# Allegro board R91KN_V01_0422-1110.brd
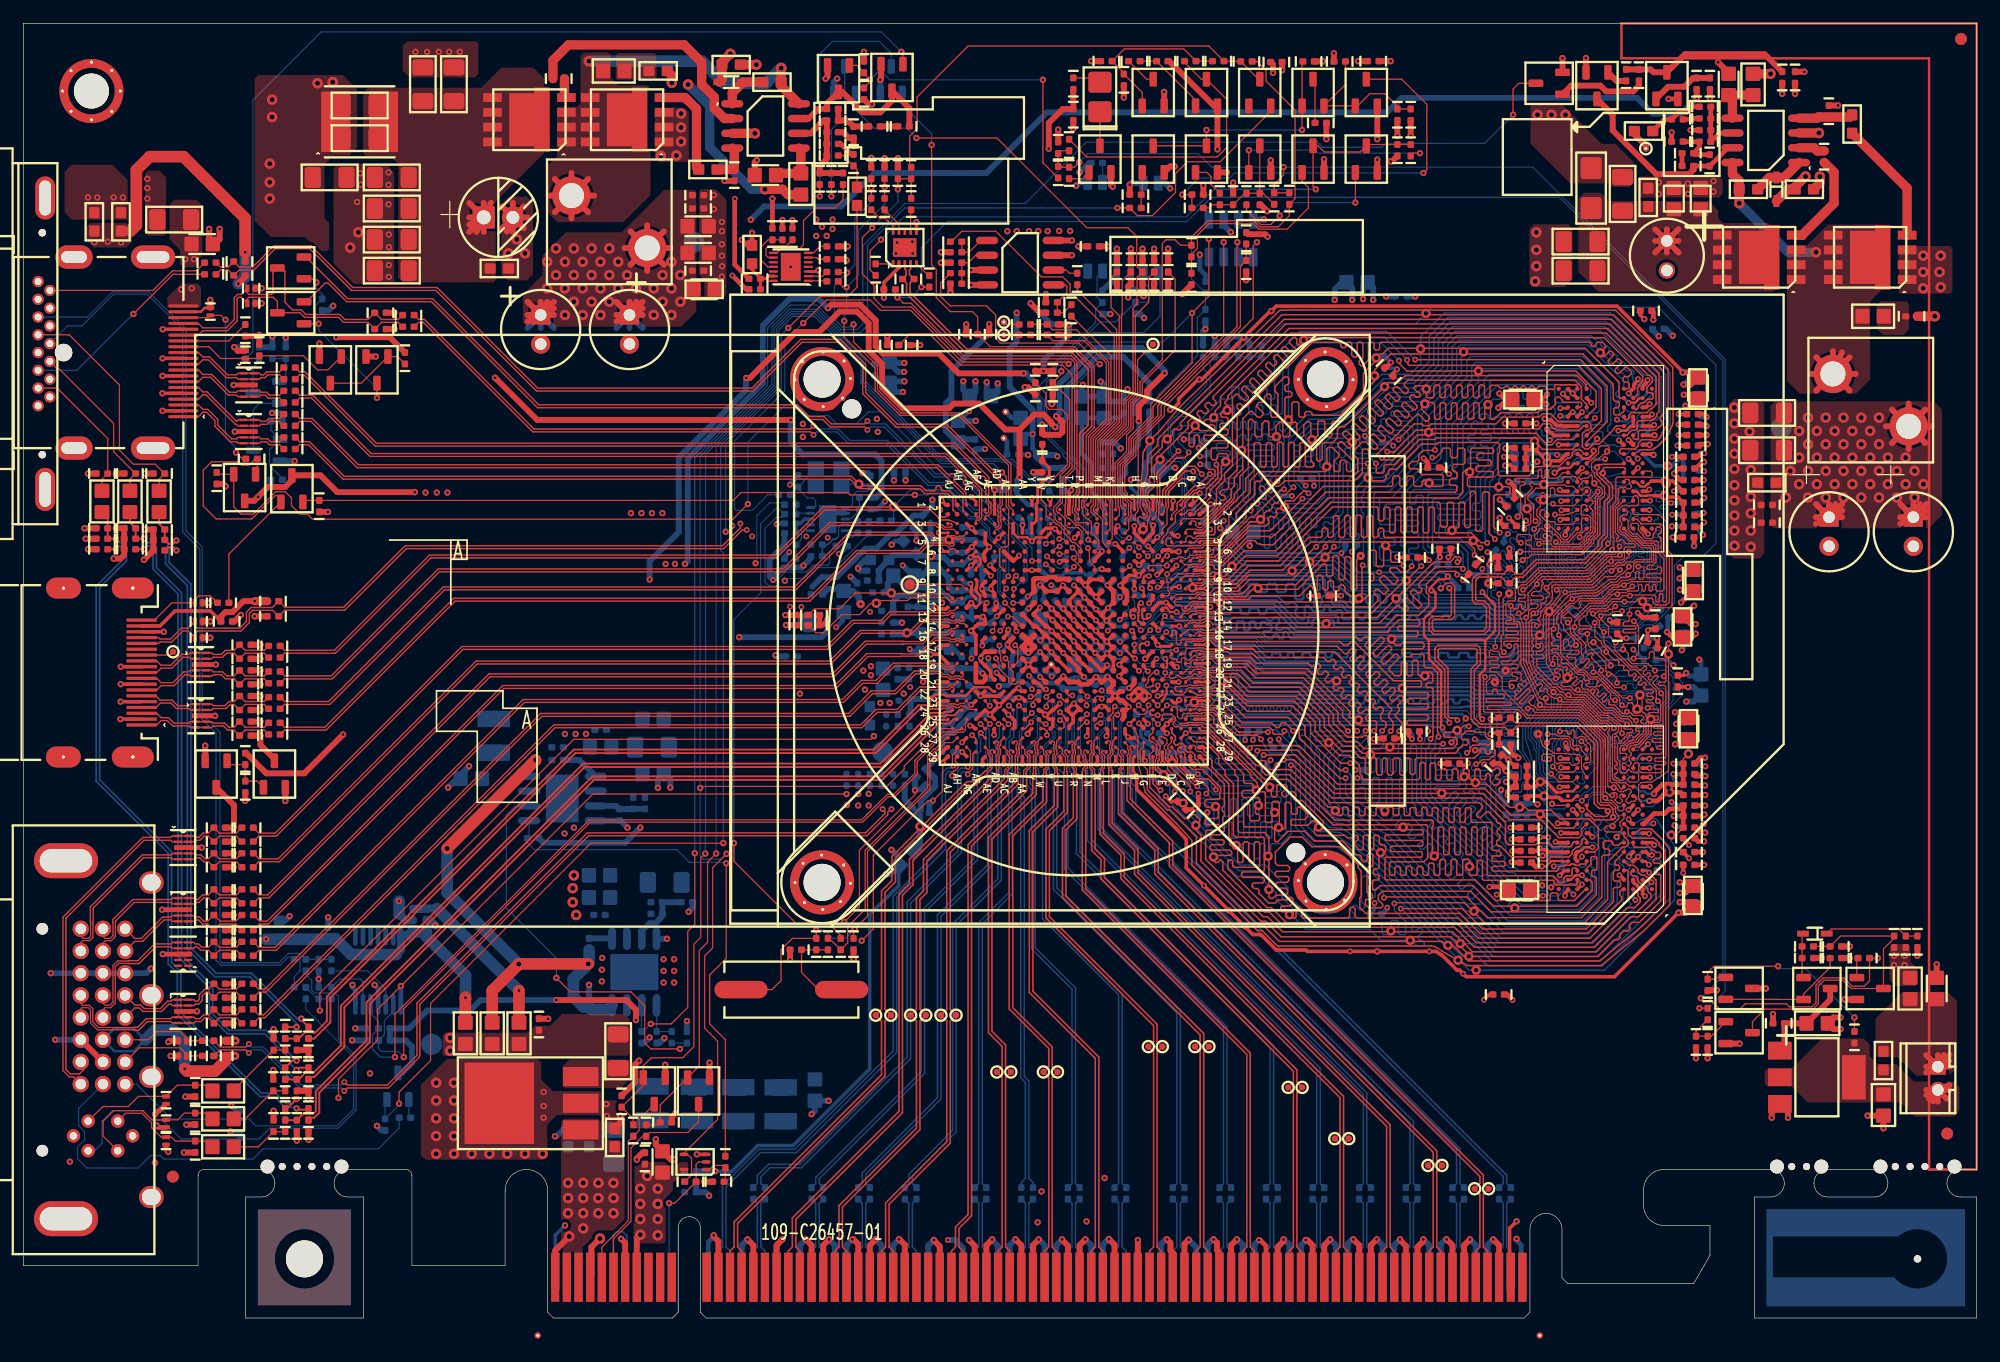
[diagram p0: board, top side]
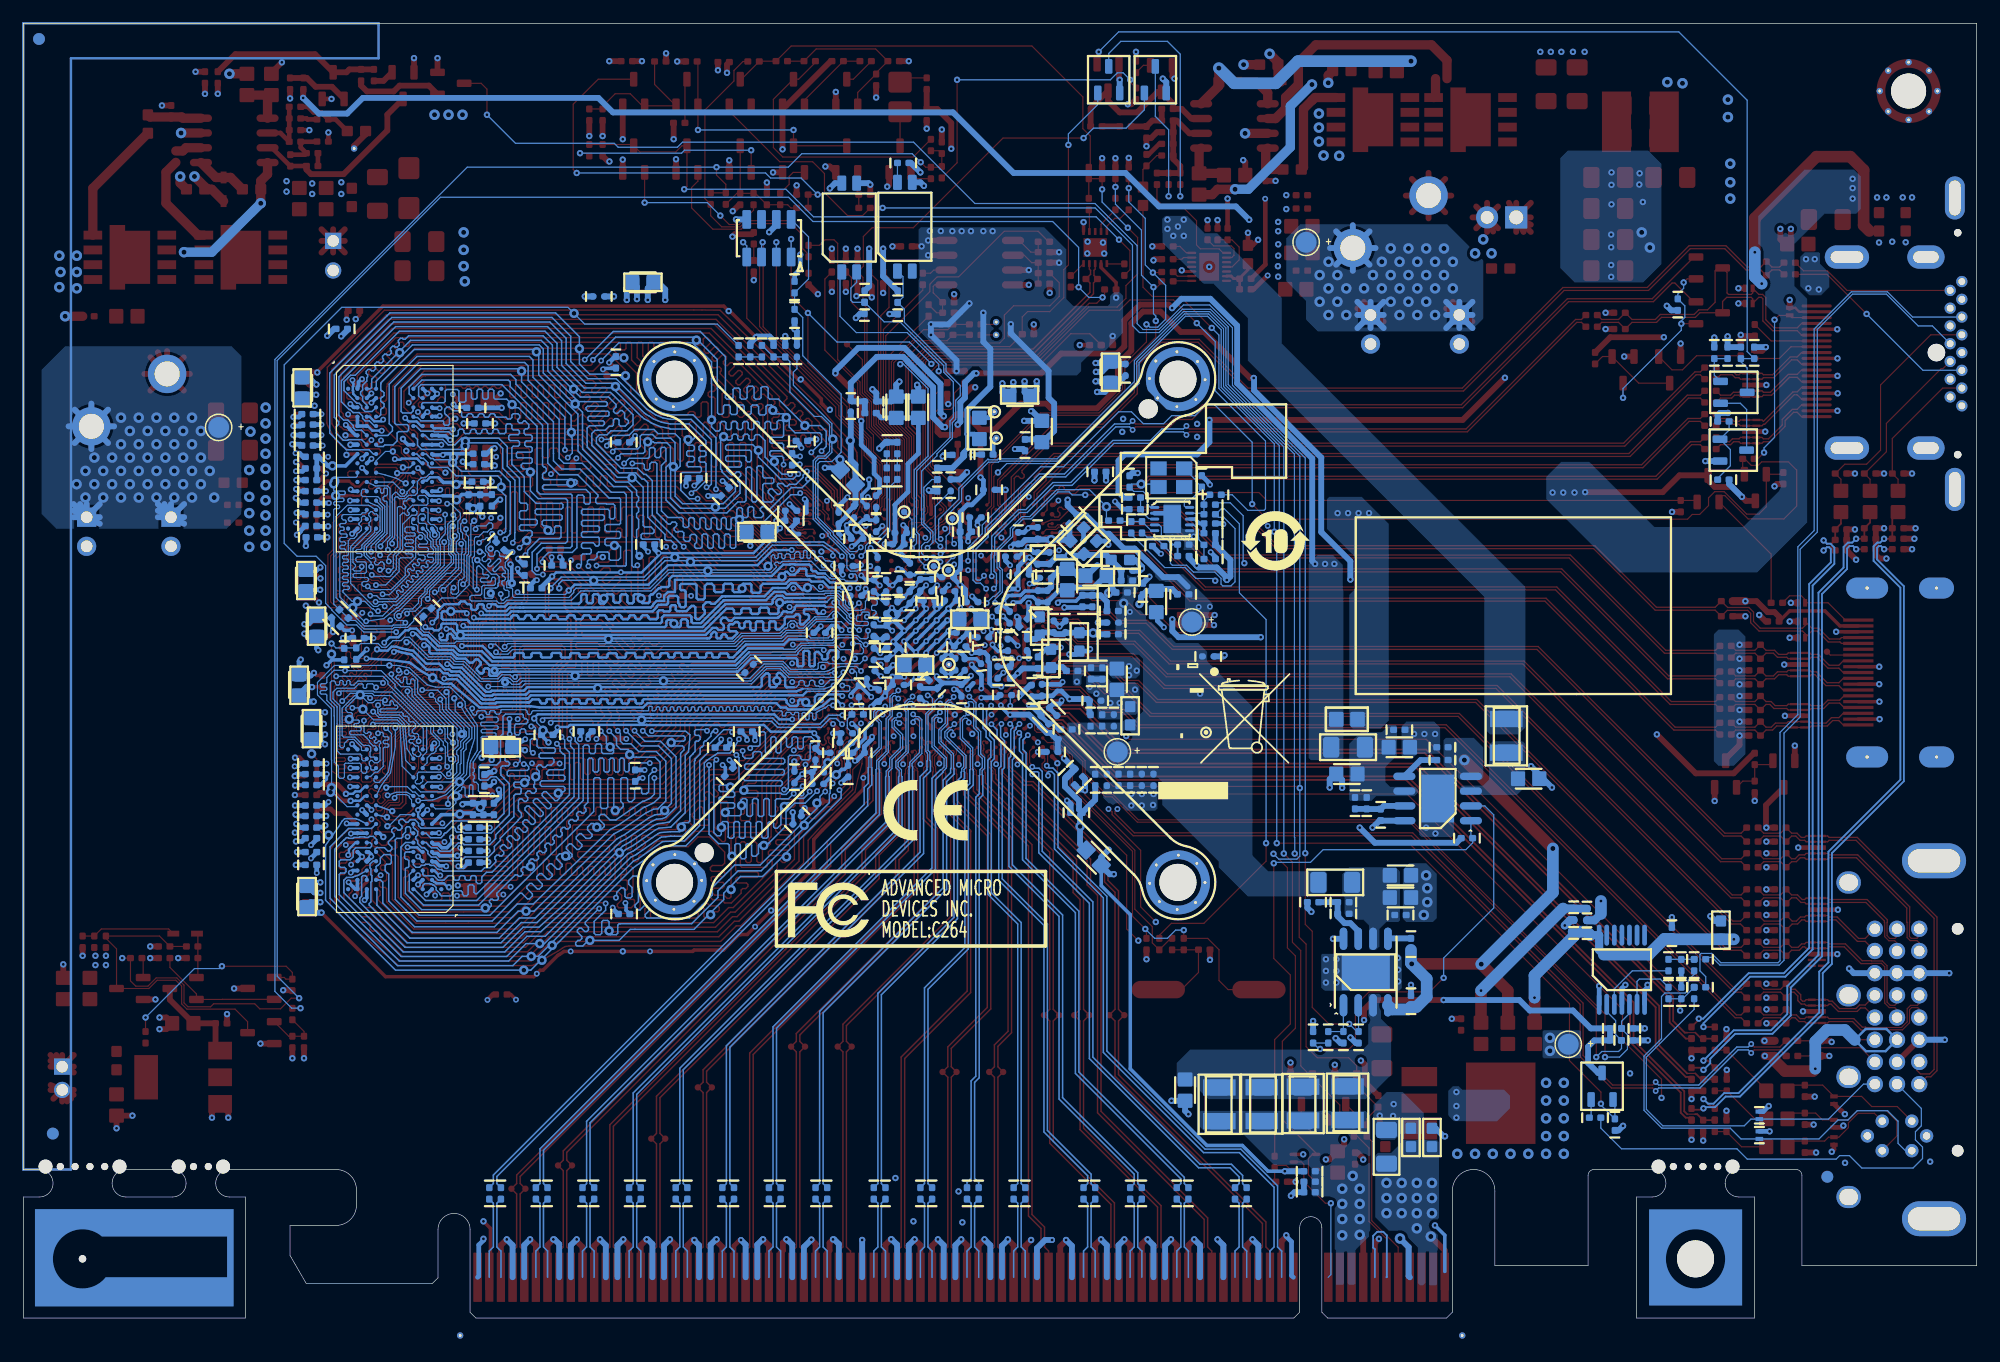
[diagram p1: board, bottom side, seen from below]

Outline 167.64 x 111.15 mm; copper layers: TOP, L2_INNER, L3_INNER, BOTTOM. Coordinates in mm from the lower left corner of the outline.
Outline path: 0,111.15 167.64,111.15 167.64,12.75 166.3,12.75 arc(165.09,11.58) 166.28,10.39 167.64,10.39 167.64,0 148.59,0 148.59,10.39 149.95,10.39 arc(150.78,10.74) 151.13,11.57 arc(150.78,12.4) 149.95,12.75 140.8,12.75 arc(139.56,12.24) 139.05,11 139.05,9.7 arc(139.56,8.46) 140.8,7.95 144.75,7.95 144.75,5.37 143.35,2.95 132.55,2.95 132.05,3.45 132.05,7.61 arc(131.65,8.58) 130.68,8.98 arc(129.7,8.58) 129.3,7.61 129.3,0.5 128.8,0 58.6,0 58.1,0.5 58.1,7.8 arc(57.15,8.7) 56.2,7.8 56.2,0.5 55.7,0 45.5,0 45,0.5 45,10.9 arc(43.17,12.75) 41.35,10.9 41.35,4.5 33.35,4.5 33.35,12.24 arc(33.2,12.6) 32.84,12.75 27.85,12.75 arc(26.67,11.57) 27.85,10.39 29.21,10.39 29.21,0 19.05,0 19.05,10.39 20.41,10.39 arc(21.24,10.74) 21.59,11.57 arc(21.24,12.4) 20.41,12.75 15.51,12.75 arc(15.15,12.6) 15,12.24 15,4.5 0,4.5 0,111.15 ; 153.67,11.57 arc(154.02,12.4) 154.85,12.75 158.84,12.75 arc(160.02,11.57) 158.84,10.39 154.85,10.39 arc(154.02,10.74) 153.67,11.57

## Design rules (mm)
net group A_VSYNC_DAC2: nets A_HSYNC_DAC2 A_VSYNC_DAC2
net group AUX2: nets AUX2N AUX2P
net group DDC1CLK: nets DDC1CLK DDC1DATA
net group DDC2CLK: nets DDC2CLK DDC2DATA
net group DDC3CLK: nets DDC3CLK DDC3DATA
net group DDC5CLK_AUX5P: nets DDC5CLK_AUX5P DDC5DATA_AUX5N
net group DPA_0: nets DPA_0N DPA_0P
net group DPA_1: nets DPA_1N DPA_1P
net group DPA_2P: nets DPA_2N DPA_2P
net group DPA_3P: nets DPA_3N DPA_3P
net group DPA_A0: nets DPA_A0N DPA_A0P
net group DPA_A1: nets DPA_A1N DPA_A1P
net group DPA_A2: nets DPA_A2N DPA_A2P
net group DPA_A3: nets DPA_A3N DPA_A3P
net group DPB_0: nets DPB_0N DPB_0P
net group DPB_1: nets DPB_1N DPB_1P
net group DPB_2: nets DPB_2N DPB_2P
net group DPB_3: nets DPB_3N DPB_3P
net group EFTX0M: nets EFTX0M EFTX0P
net group EFTX1M: nets EFTX1M EFTX1P
net group EFTX2M: nets EFTX2M EFTX2P
net group EFTX3M: nets EFTX3M EFTX3P
net group EFTX4M: nets EFTX4M EFTX4P
net group EFTX5M: nets EFTX5M EFTX5P
net group FB: nets NFB PFB
net group MEM_CALR0: nets MEM_CALRN0 MEM_CALRP0
net group PCIE_CALR: nets PCIE_CALRN PCIE_CALRP
net group PCIE_PH: nets GPU_DMINUS GPU_DPLUS
net group PER0: nets PERN0 PERP0
net group PER1: nets PERN1 PERP1
net group PER2: nets PERN2 PERP2
net group PER3: nets PERN3 PERP3
net group PER4: nets PERN4 PERP4
net group PER5: nets PERN5 PERP5
net group PER6: nets PERN6 PERP6
net group PER7: nets PERN7 PERP7
net group PER8: nets PERN8 PERP8
net group PER9: nets PERN9 PERP9
net group PER10: nets PERN10 PERP10
net group PER11: nets PERN11 PERP11
net group PER12: nets PERN12 PERP12
net group PER13: nets PERN13 PERP13
net group PER14: nets PERN14 PERP14
net group PER15: nets PERN15 PERP15
net group DVP_R: nets GENERICC GENERICD GPIO_1 GPIO_2 GPIO_3_SMBDATA GPIO_4_SMBCLK GPIO_5 GPIO_8_SO
net group M_DQMA#: nets M_DQMA#0 M_DQMA#1 M_DQMA#2 M_DQMA#3 M_DQMA#4 M_DQMA#5 M_DQMA#6 M_DQMA#7
net group M_MAA: nets M_MAA0 M_MAA1 M_MAA2 M_MAA3 M_MAA4 M_MAA5 M_MAA6 M_MAA7 M_MAA8 M_MAA9 M_MAA10 M_MAA11 M_MAA12 M_MAA13 M_MAA14
net group M_MDA: nets M_MDA0 M_MDA1 M_MDA2 M_MDA3 M_MDA4 M_MDA5 M_MDA6 M_MDA7 M_MDA8 M_MDA9 M_MDA10 M_MDA11 M_MDA12 M_MDA13 M_MDA14 M_MDA15 M_MDA16 M_MDA17 M_MDA18 M_MDA19 M_MDA20 M_MDA21 M_MDA22 M_MDA23 M_MDA24 M_MDA25 M_MDA26 M_MDA27 M_MDA28 M_MDA29 M_MDA30 M_MDA31 M_MDA32 M_MDA33 M_MDA34 M_MDA35 M_MDA36 M_MDA37 M_MDA38 M_MDA39 M_MDA40 M_MDA41 M_MDA42 M_MDA43 M_MDA44 M_MDA45 M_MDA46 M_MDA47 M_MDA48 M_MDA49 M_MDA50 M_MDA51 M_MDA52 M_MDA53 M_MDA54 M_MDA55 M_MDA56 M_MDA57 M_MDA58 M_MDA59 M_MDA60 M_MDA61 M_MDA62 M_MDA63
net group M_QSA: nets M_QSA0 M_QSA1 M_QSA2 M_QSA3 M_QSA4 M_QSA5 M_QSA6 M_QSA7
net group M_QSA#: nets M_QSA#0 M_QSA#1 M_QSA#2 M_QSA#3 M_QSA#4 M_QSA#5 M_QSA#6 M_QSA#7
net group MEM_ADD: nets BA0 BA1 BA2 CASA#0 CASA#1 CKEA0 CKEA1 CSA#0_0 CSA#1_0 ODTA0 RASA#0 RASA#1 WEA#0 WEA#1
net group MEM_CLK: nets CLKA0 CLKA1 CLKA#0 CLKA#1
net group NET_PERST#: nets PERST#
net group NET_PRESENCE: nets PRESENCE
net group PCIE_SP: nets PCIE_REFCLKN PCIE_REFCLKP PCIE_TX0N PCIE_TX0P PCIE_TX1N PCIE_TX1P PCIE_TX2N PCIE_TX2P PCIE_TX3N PCIE_TX3P PCIE_TX4N PCIE_TX4P PCIE_TX5N PCIE_TX5P PCIE_TX6N PCIE_TX6P PCIE_TX7N PCIE_TX7P PCIE_TX8N PCIE_TX8P PCIE_TX9N PCIE_TX9P PCIE_TX10N PCIE_TX10P PCIE_TX11N PCIE_TX11P PCIE_TX12N PCIE_TX12P PCIE_TX13N PCIE_TX13P PCIE_TX14N PCIE_TX14P PCIE_TX15N PCIE_TX15P PETN0_GFXRN0 PETN1_GFXRN1 PETN2_GFXRN2 PETN3_GFXRN3 PETN4_GFXRN4 PETN5_GFXRN5 PETN6_GFXRN6 PETN7_GFXRN7 PETN8_GFXRN8 PETN9_GFXRN9 PETN10_GFXRN10 PETN11_GFXRN11 PETN12_GFXRN12 PETN13_GFXRN13 PETN14_GFXRN14 PETN15_GFXRN15 PETP0_GFXRP0 PETP1_GFXRP1 PETP2_GFXRP2 PETP3_GFXRP3 PETP4_GFXRP4 PETP5_GFXRP5 PETP6_GFXRP6 PETP7_GFXRP7 PETP8_GFXRP8 PETP9_GFXRP9 PETP10_GFXRP10 PETP11_GFXRP11 PETP12_GFXRP12 PETP13_GFXRP13 PETP14_GFXRP14 PETP15_GFXRP15
net group RGB: nets A_B_DAC1 A_BB_DAC1 A_G_DAC1 A_GB_DAC1 A_R_DAC1 A_RB_DAC1 B_DAC2 BB_DAC2 G_DAC2 GB_DAC2 R_DAC2 RB_DAC2
net group TMDS: nets DPB_AUXN DPB_AUXP DPB_C0N DPB_C0P DPB_C1N DPB_C1P DPB_C2N DPB_C2P DPB_C3N DPB_C3P DPE_TX0N DPE_TX0P DPE_TX1N DPE_TX1P DPE_TX2N DPE_TX2P DPE_TXCAN DPE_TXCAP DPF_TX3N DPF_TX3P DPF_TX4N DPF_TX4P DPF_TX5N DPF_TX5P EFTXCM EFTXCP
nets with their own width: min track width 0.3; nets +MVDD

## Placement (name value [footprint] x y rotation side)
B2  BLM15BD121SN1  [SMIND1005_0_5H]  78.11 50.53 270 bottom
B5  BLM15BD121SN1  [SMIND1005_0_5H]  96.63 78.29 180 bottom
B6  BLM15BD121SN1  [SMIND1005_0_5H]  76.05 51.3 0 bottom
B7  BLM15BD121SN1  [SMIND1005_0_5H]  73.38 62.28 270 bottom
B8  BLM15BD121SN1  [SMIND1005_0_5H]  68.1 62.12 270 bottom
B9  BLM15BD121SN1  [SMIND1005_0_5H]  94.45 70.1 179.8 bottom
B11  BLM15BD121SN1  [SMIND1005_0_5H]  75.65 46.2 180 bottom
B12  BLM15BD121SN1  [SMIND1005_0_5H]  94.93 77.69 90 bottom
B71  BLM15BD121SN1  [SMIND1005_0_5H]  68.08 65.42 270 bottom
B72  BLM15BD121SN1  [SMIND1005_0_5H]  65.83 67.38 270 bottom
B702  60R  [IND_3216_4515]  134.55 97 180 top
B800  BLM15AG121SN1D  [SMIND1005_0_5H]  86.75 67.5 90 bottom
B801  BLM15AG121SN1D  [SMIND1005_0_5H]  87.45 75.5 0 top
B850  220R_2A  [RES1608_2012_1_1H]  54.05 51.4 90 bottom
B1500  BLM15AG121SN1D  [SMIND1005_0_5H]  74.15 58.7 270 bottom
B1502  BLM15BD121SN1  [SMIND1005_0_5H]  77.63 55.55 270 bottom
B2503  BLM15AG121SN1D  [SMIND1005_0_5H]  72.93 63.31 270 bottom
B2505  BLM15BD121SN1  [SMIND1005_0_5H]  77.52 68.55 225 bottom
B4001  26R_600mA  [RES1608_2012_1_1H]  161.93 28.29 0 top
C3  0.1uF  [CAP1005_0_55H]  62.65 10.7 180 bottom
C4  0.1uF  [CAP1005_0_55H]  63.65 10.7 180 bottom
C5  0.1uF  [CAP1005_0_55H]  67.65 10.7 180 bottom
C6  0.1uF  [CAP1005_0_55H]  68.65 10.7 180 bottom
C7  0.1uF  [CAP1005_0_55H]  71.65 10.7 180 bottom
C8  0.1uF  [CAP1005_0_55H]  57.25 10.8 270 bottom
C9  0.1uF  [CAP1005_0_55H]  72.65 10.7 180 bottom
C10  0.1uF  [CAP1005_0_55H]  75.65 10.7 180 bottom
C11  0.1uF  [CAP1005_0_55H]  76.65 10.7 180 bottom
C12  0.1uF  [CAP1005_0_55H]  81.65 10.7 180 bottom
C13  0.1uF  [CAP1005_0_55H]  82.65 10.7 180 bottom
C14  10uF  [CAP3216_1_80H]  50.65 14.7 0 bottom
C15  0.1uF  [CAP1005_0_55H]  85.65 10.7 180 bottom
C16  0.1uF  [CAP1005_0_55H]  86.65 10.7 180 bottom
C17  0.1uF  [CAP1005_0_55H]  89.65 10.7 180 bottom
C18  0.1uF  [CAP1005_0_55H]  90.65 10.7 180 bottom
C19  0.1uF  [CAP1005_0_55H]  93.65 10.7 180 bottom
C20  0.15uF  [CAP1608]  48.55 15.5 0 bottom
C21  0.15uF  [CAP1608]  46.75 15.5 0 bottom
C22  0.1uF  [CAP1005_0_55H]  94.65 10.7 180 bottom
C23  0.1uF  [CAP1005_0_55H]  98.65 10.7 180 bottom
C24  0.1uF  [CAP1005_0_55H]  99.65 10.7 180 bottom
C25  0.1uF  [CAP1005_0_55H]  102.65 10.7 180 bottom
C26  0.1uF  [CAP1005_0_55H]  103.65 10.7 180 bottom
C27  10uF  [CAP1608_2012_1_53H]  54.85 13.4 180 top
C28  0.1uF  [CAP1005_0_55H]  106.65 10.7 180 bottom
C29  0.1uF  [CAP1005_0_55H]  107.65 10.7 180 bottom
C30  0.1uF  [CAP1005_0_55H]  110.65 10.7 180 bottom
C31  0.1uF  [CAP1005_0_55H]  111.65 10.7 180 bottom
C32  0.1uF  [CAP1005_0_55H]  114.65 10.7 180 bottom
C33  0.1uF  [CAP1005_0_55H]  53.35 13.7 180 top
C34  1uF  [CAP1005_0_55H]  57.25 11.7 90 bottom
C35  10nF  [CAP1005]  57.25 12.6 270 bottom
C36  0.1uF  [CAP1005_0_55H]  115.65 10.7 180 bottom
C37  0.1uF  [CAP1005_0_55H]  118.65 10.7 180 bottom
C38  0.1uF  [CAP1005_0_55H]  119.65 10.7 180 bottom
C39  0.1uF  [CAP1005_0_55H]  122.65 10.7 180 bottom
C40  0.1uF  [CAP1005_0_55H]  123.65 10.7 180 bottom
C41  0.1uF  [CAP1005_0_55H]  126.65 10.7 180 bottom
C42  0.1uF  [CAP1005_0_55H]  127.65 10.7 180 bottom
C43  0.1uF  [CAP1005]  115.85 107.9 90 top
C44  0.1uF  [CAP1005]  107.54 107.82 270 top
C47  0.1uF  [CAP1005]  152.05 106.5 180 top
C53  0.1uF  [CAP1005_0_55H]  76.75 61.55 0 bottom
C57  0.1uF  [CAP1005_0_55H]  90.11 103.3 0 top
C58  10uF  [CAP1608_2012_1_53H]  96.87 72.17 315 bottom
C59  0.1uF  [CAP1005_0_55H]  80.55 61.95 0 bottom
C61  1uF  [CAP1005_0_55H]  96.35 69.2 180 bottom
C62  0.1uF  [CAP1005_0_55H]  97.66 68.67 0 bottom
C63  10uF  [CAP1608_2012_1_53H]  78.05 63.4 0 bottom
C64  1uF  [CAP1005_0_55H]  79.75 61.95 0 bottom
C66  0.1uF  [CAP1005_0_55H]  71.55 62.59 0 bottom
C67  1uF  [CAP1005_0_55H]  82.99 60.15 0 bottom
C68  10uF  [CAP1608_2012_1_53H]  70.41 61.51 180 bottom
C70  1uF  [CAP1005_0_55H]  94.45 68 180 bottom
C71  0.1uF  [CAP1005_0_55H]  96.09 66.9 270.7 bottom
C73  1uF  [CAP1005_0_55H]  77.27 43.38 270 bottom
C74  10nF  [CAP1005]  77.05 46.8 135 bottom
C75  0.1uF  [CAP1005_0_55H]  77.75 46.1 135 bottom
C77  10uF  [CAP1608_2012_1_53H]  90.83 78.19 0 bottom
C78  10uF  [CAP1608_2012_1_53H]  92.73 78.19 0 bottom
C79  1uF  [CAP1005_0_55H]  92.34 67.41 90 bottom
C80  0.1uF  [CAP1005_0_55H]  92.53 66.42 90 bottom
C82  12pF  [CAP1005]  66.29 31.62 270 top
C83  12pF  [CAP1005]  71.25 32.1 0 top
C85  1uF  [CAP1005_0_55H]  92.44 62.98 180 bottom
C86  0.1uF  [CAP1005_0_55H]  93.57 60.96 0 bottom
C87  0.1uF  [CAP1005_0_55H]  92.62 60.98 0 bottom
C88  10uF  [CAP1608_2012_1_53H]  75.58 63.73 270 bottom
C89  10uF  [CAP1608_2012_1_53H]  75.78 39.52 135 bottom
C90  0.1uF  [CAP1005_0_55H]  65.83 68.21 90 bottom
C91  0.1uF  [CAP1005_0_55H]  68.08 66.4 90 bottom
C92  12pF  [CAP1005]  72.7 71.81 0 bottom
C93  12pF  [CAP1005]  66.5 71.83 0 bottom
C94  0.1uF  [CAP1005]  92.63 72.49 0 bottom
C95  0.1uF  [CAP1005]  93.53 72.49 0 bottom
C120  10nF  [CAP1005]  94.91 55.22 225 bottom
C121  10nF  [CAP1005]  99.66 48.41 0 bottom
C122  10nF  [CAP1005]  126.5 47.98 315 top
C123  10nF  [CAP1005]  123.62 62.66 90 bottom
C124  10nF  [CAP1005]  96.94 64.56 270 bottom
C125  0.1uF  [CAP1005_0_55H]  124.35 64.28 145.1 top
C126  0.1uF  [CAP1005_0_55H]  139.82 57.77 61.6 top
C127  0.1uF  [CAP1005_0_55H]  107.09 46.88 45 bottom
C128  0.1uF  [CAP1005_0_55H]  101.78 68.45 90 bottom
C129  0.1uF  [CAP1005_0_55H]  116.08 34.69 270 bottom
C130  10uF  [CAP1608_2012_1_53H]  143.98 54.36 0 bottom
C131  10uF  [CAP1608_2012_1_53H]  142.91 50.59 0 bottom
C132  10uF  [CAP1608_2012_1_53H]  104.67 67.49 90 bottom
C133  10uF  [CAP1608_2012_1_53H]  143.71 79.85 0 bottom
C134  1uF  [CAP1005_0_55H]  96.19 62.01 90 bottom
C135  1uF  [CAP1005_0_55H]  94.32 64.78 0 bottom
C136  1uF  [CAP1005_0_55H]  121.81 64.61 90 bottom
C137  1uF  [CAP1005_0_55H]  94.65 62.88 180 bottom
C138  1uF  [CAP1005_0_55H]  118.25 87.7 90 bottom
C139  1uF  [CAP1005_0_55H]  101.75 69.3 90 bottom
C140  1uF  [CAP1005_0_55H]  99.3 58.83 270 bottom
C141  0.1uF  [CAP1005_0_55H]  107.42 70.92 225 bottom
C142  0.1uF  [CAP1005_0_55H]  126.62 27.77 90 top
C143  1uF  [CAP1005_0_55H]  89.69 62.91 0 bottom
C144  1uF  [CAP1005_0_55H]  94.93 78.69 90 bottom
C145  1uF  [CAP1005_0_55H]  65.95 56.8 90 bottom
C146  1uF  [CAP1005_0_55H]  73.65 46.2 180 bottom
C147  4.7uF  [CAP1608]  72.65 51.7 0 bottom
C148  1uF  [CAP1005_0_55H]  74.15 59.7 270 bottom
C149  0.1uF  [CAP1005_0_55H]  75.05 51.3 0 bottom
C150  1uF  [CAP1005_0_55H]  94.22 53.42 0 bottom
C151  1uF  [CAP1005_0_55H]  92.55 54.35 90 bottom
C152  1uF  [CAP1005_0_55H]  90.68 53.71 180 bottom
C153  1uF  [CAP1005_0_55H]  89.57 54.4 315 bottom
C154  1uF  [CAP1005_0_55H]  76 55.34 180 bottom
C155  1uF  [CAP1005_0_55H]  75.03 55.33 180 bottom
C156  0.1uF  [CAP1005_0_55H]  84.75 71.1 90 bottom
C158  10uF  [CAP1608_2012_1_53H]  73.78 54.84 180 bottom
C161  1uF  [CAP1005_0_55H]  79.35 48.6 270 bottom
C162  1uF  [CAP1005_0_55H]  70.65 46.2 180 bottom
C163  0.1uF  [CAP1005_0_55H]  74.65 46.2 180 bottom
C164  0.1uF  [CAP1005_0_55H]  87.25 57.66 270 bottom
C165  0.1uF  [CAP1005_0_55H]  85.51 56.67 173.5 bottom
C167  0.1uF  [CAP1005_0_55H]  87.43 74.09 270 bottom
C168  1uF  [CAP1005_0_55H]  88.08 61.6 270 bottom
C169  1uF  [CAP1005_0_55H]  88.74 56.12 180 bottom
C170  1uF  [CAP1005_0_55H]  84.91 74.12 90 bottom
C171  1uF  [CAP1005_0_55H]  75.22 72.64 90 bottom
C172  1uF  [CAP1005_0_55H]  94.65 57 0 bottom
C173  1uF  [CAP1005_0_55H]  88.19 62.39 270 bottom
C174  4.7uF  [CAP1608]  86.41 59.99 90 bottom
C175  4.7uF  [CAP1608]  74.33 81.2 0 bottom
C176  4.7uF  [CAP1608]  91.14 56.06 270 bottom
C177  4.7uF  [CAP1608]  58.43 88.32 90 top
C179  1uF  [CAP1005_0_55H]  72.65 46.2 180 bottom
C180  1uF  [CAP1005_0_55H]  74.05 51.3 0 bottom
C181  1uF  [CAP1005_0_55H]  71.65 46.2 180 bottom
C182  1uF  [CAP1005_0_55H]  57.91 89.92 90 top
C183  1uF  [CAP1005_0_55H]  87.07 58.84 90 bottom
C184  1uF  [CAP1005_0_55H]  94.66 59.02 180 bottom
C185  1uF  [CAP1005_0_55H]  87.66 56.12 180 bottom
C186  1uF  [CAP1005_0_55H]  73.05 81.4 0 bottom
C187  1uF  [CAP1005_0_55H]  89.9 61.58 90 bottom
C188  1uF  [CAP1005_0_55H]  93.6 62.85 180 bottom
C189  1uF  [CAP1005_0_55H]  93.56 58.98 180 bottom
C190  1uF  [CAP1005_0_55H]  90.66 62.92 0 bottom
C193  0.1uF  [CAP1005_0_55H]  93.53 56.09 180 bottom
C194  1uF  [CAP1005_0_55H]  93.03 57.55 270 bottom
C195  1uF  [CAP1005_0_55H]  91.57 61.86 0 bottom
C196  10uF  [CAP1608_2012_1_53H]  82.11 79.15 90 bottom
C295  1uF  [CAP1005_0_55H]  95.95 48.52 90 bottom
C297  1uF  [CAP1005_0_55H]  97.05 49.4 270 bottom
C300  1uF  [CAP1005]  127.65 68 90 top
C301  1uF  [CAP1005]  142.94 71.94 270 top
C302  1uF  [CAP1005]  128.55 73.3 270 bottom
C303  1uF  [CAP1005]  101.66 73.72 180 bottom
C304  1uF  [CAP1005]  140.31 84.92 90 bottom
C305  1uF  [CAP1005]  143.25 77.6 270 top
C306  1uF  [CAP1005]  126.71 66.28 315 bottom
C307  1uF  [CAP1005]  142.95 38.9 270 top
C308  1uF  [CAP1005]  113.94 66.41 270 bottom
C309  1uF  [CAP1005]  142.95 41.2 270 top
C310  1uF  [CAP1005]  128.95 42.1 90 top
C311  1uF  [CAP1005]  128.95 39.1 90 top
C312  1uF  [CAP1005]  128.95 40.1 90 top
C313  1uF  [CAP1005]  142.88 67.03 90 bottom
C314  1uF  [CAP1005]  116.11 75.18 270 bottom
C315  1uF  [CAP1005]  117.21 49.76 90 top
C316  1uF  [CAP1005]  138.88 58.37 90 bottom
C317  1uF  [CAP1005]  128.95 40.1 270 bottom
C318  1uF  [CAP1005]  143.25 75.8 90 bottom
C319  1uF  [CAP1005]  143.25 76.7 90 bottom
C320  1uF  [CAP1005]  142.95 70.99 90 bottom
C321  1uF  [CAP1005]  128.55 74.2 270 bottom
C322  1uF  [CAP1005]  142.95 47.6 90 bottom
C323  1uF  [CAP1005]  128.95 42.1 270 bottom
C324  1uF  [CAP1005]  143.25 77.6 90 bottom
C325  1uF  [CAP1005]  116.78 82.05 180 bottom
C326  1uF  [CAP1005]  128.45 76.8 90 top
C327  1uF  [CAP1005]  128.45 76.8 270 bottom
C328  1uF  [CAP1005]  121.02 73 90 top
C329  1uF  [CAP1005]  142.95 43.1 90 bottom
C330  1uF  [CAP1005]  122.79 47.6 90 top
C331  1uF  [CAP1005]  142.95 40 90 bottom
C332  1uF  [CAP1005]  119.34 50.34 90 top
C333  1uF  [CAP1005]  115.13 46.56 180 bottom
C334  1uF  [CAP1005]  99.4 44 225 top
C335  1uF  [CAP1005]  101.46 46.43 180 bottom
C336  1uF  [CAP1005]  128.06 46.17 180 bottom
C337  1uF  [CAP1005]  143.25 74.9 270 top
C338  1uF  [CAP1005]  142.95 40 270 top
C339  1uF  [CAP1005]  119.31 50.37 270 bottom
C340  1uF  [CAP1005]  142.95 42.1 90 bottom
C341  1uF  [CAP1005]  124.62 64.25 180 bottom
C342  1uF  [CAP1005]  143.25 76.7 270 top
C343  1uF  [CAP1005]  127.62 70.03 315 top
C344  1uF  [CAP1005]  128.95 41.1 90 top
C345  1uF  [CAP1005]  143.25 74.9 90 bottom
C346  1uF  [CAP1005]  142.95 41.2 90 bottom
C347  1uF  [CAP1005]  142.95 70 90 bottom
C348  1uF  [CAP1005]  142.95 69 90 bottom
C349  1uF  [CAP1005]  110.11 72.11 90 bottom
C350  1uF  [CAP1005]  142.95 68 90 bottom
C351  1uF  [CAP1005]  117.18 81.22 45 top
C352  1uF  [CAP1005]  142.95 38.9 90 bottom
C353  1uF  [CAP1005]  119.19 65.29 270 top
C354  1uF  [CAP1005]  142.88 67.03 270 top
C355  0.1uF  [CAP1005_0_55H]  140.07 59.66 180 top
C356  0.1uF  [CAP1005_0_55H]  136.79 59.24 180 top
C357  0.1uF  [CAP1005_0_55H]  142.94 45.76 270.5 bottom
C358  0.1uF  [CAP1005_0_55H]  122.02 66.04 270 top
C359  0.1uF  [CAP1005_0_55H]  142.95 44 270 bottom
C360  0.1uF  [CAP1005_0_55H]  128.95 39.1 90 bottom
C361  0.1uF  [CAP1005_0_55H]  107.78 48.98 90 bottom
C362  0.1uF  [CAP1005_0_55H]  142.94 73.94 90 top
C363  0.1uF  [CAP1005_0_55H]  142.94 72.94 90 top
C364  10uF  [CAP1608_2012_1_53H]  128.4 36.71 270 top
C365  10uF  [CAP1608_2012_1_53H]  143.29 63.31 0 top
C366  10uF  [CAP1608_2012_1_53H]  142.91 50.59 180 top
C367  10uF  [CAP1608_2012_1_53H]  143.38 63.31 180 bottom
C368  10uF  [CAP1608_2012_1_53H]  143.72 79.84 180 top
C369  10uF  [CAP1608_2012_1_53H]  142.4 59.34 0 top
C370  0.1uF  [CAP1005_0_55H]  105.56 50.35 90 bottom
C371  0.1uF  [CAP1005_0_55H]  111.55 62 90 top
C372  0.1uF  [CAP1005_0_55H]  143.25 75.8 90 top
C373  0.1uF  [CAP1005_0_55H]  139.26 86.47 90 top
C374  0.1uF  [CAP1005_0_55H]  122.67 50.06 90 bottom
C375  0.1uF  [CAP1005_0_55H]  142.95 46.7 270 bottom
C376  0.1uF  [CAP1005_0_55H]  128.95 41.1 90 bottom
C377  0.1uF  [CAP1005_0_55H]  141.98 54.67 180 top
C378  10uF  [CAP1608_2012_1_53H]  143.29 36.18 180 bottom
C379  10uF  [CAP1608_2012_1_53H]  143.29 36.18 0 top
C380  10uF  [CAP1608_2012_1_53H]  126.57 49.03 90 bottom
C381  10uF  [CAP1608_2012_1_53H]  142.47 59.4 180 bottom
C382  10uF  [CAP1608_2012_1_53H]  114.47 88.92 90 bottom
C383  10uF  [CAP1608_2012_1_53H]  128.69 78.85 270 top
C384  1uF  [CAP1005]  101.23 42.76 225 bottom
C385  1uF  [CAP1005]  100.82 75.3 90 bottom
C386  1uF  [CAP1005]  129.09 78.14 270 bottom
C410  100nF  [CAP1608]  50.75 15.5 180 top
C411  1uF_6.3V  [CAP1005]  44.25 25.2 180 top
C413  0.1uF  [CAP1005_0_55H]  142.95 45.8 90 top
C438  0.1uF  [CAP1005_0_55H]  128.55 45.6 270 top
C448  0.1uF  [CAP1005_0_55H]  129.43 70.19 180 bottom
C463  0.1uF  [CAP1005_0_55H]  142.95 70 90 top
C486  0.1uF  [CAP1005_0_55H]  129.05 43.7 0 bottom
C487  0.1uF  [CAP1005_0_55H]  142.95 44 90 top
C488  0.1uF  [CAP1005_0_55H]  128.45 74.7 270 top
C489  0.1uF  [CAP1005_0_55H]  142.94 73.94 270 bottom
C499  10nF  [CAP1005]  127.16 49.23 90 top
C500  10nF  [CAP1005]  127.04 65.37 90 top
C603  220nF  [CAP1608_2012_1_53H]  63.69 98.12 270 top
C605  0.1uF  [CAP1608]  64.25 106.1 90 top
C606  0.15uF  [CAP1608]  60.75 107.6 90 top
C608  1uF  [CAP1608_0_89H]  54.48 107.06 270 top
C609  10uF  [CAP3216_1_80H]  26.29 97.92 90 top
C611  15nF  [CAP1005]  75.55 102.3 270 top
C612  150pF  [CAP1005]  69.45 103.8 90 top
C613  3.9nF  [CAP1005]  71.25 99.4 180 top
C615  10uF  [CAP3216_1_80H]  36.96 105.92 180 top
C616  10uF  [CAP3216_1_80H]  31.62 92.58 270 top
C617  10uF  [CAP3216_1_80H]  31.62 89.92 270 top
C619  10uF  [CAP3216_1_80H]  34.29 105.92 180 top
C620  10uF  [CAP3216_1_80H]  31.62 97.92 270 top
C621  10uF  [CAP3216_1_80H]  31.62 95.25 270 top
C623  0.1uF  [CAP1005_0_55H]  57.91 96.39 90 top
C624  15nF  [CAP1005]  57.91 95.25 90 top
C625  820uF  [CAP_E_6M3X9M0_P2M5]  44.4 84.86 270 top
C626  820uF  [CAP_E_6M3X9M0_P2M5]  52.02 84.86 270 top
C629  10uF  [CAP1608_2012_1_53H]  57.91 91.44 90 top
C630  10uF  [CAP1608_2012_1_53H]  57.91 93.73 90 top
C631  270uF  [CAP_E_6M3X12M5_P2M5]  40.77 94.49 0 top
C633  0.15uF  [CAP1608]  40.85 90.1 90 top
C703  220nF  [CAP1608_2012_1_53H]  146.35 105.9 180 top
C705  0.1uF  [CAP1608]  148.05 96.9 270 top
C706  0.15uF  [CAP1608]  152.85 96.9 90 top
C708  10nF  [CAP1005]  162.05 86 90 top
C711  15nF  [CAP1005]  142.85 98.9 270 top
C712  150pF  [CAP1005]  144.72 99.38 180 top
C713  3.9nF  [CAP1005]  141.95 102.9 90 top
C715  10uF  [CAP3216_1_80H]  133.65 89.91 270 top
C716  10uF  [CAP3216_1_80H]  133.65 92.41 270 top
C717  4.7uF  [CAP1608_2012_1_40H]  141.65 96.1 180 top
C718  0.15uF  [CAP1608]  139.45 96.2 180 top
C719  4.7uF  [CAP1608_2012_1_40H]  143.95 96.1 180 top
C723  10uF  [CAP3216_1_524H]  149.65 74.5 270 top
C724  10uF  [CAP3216_1_524H]  149.65 77.7 270 top
C725  0.1uF  [CAP1005_0_55H]  149.63 68.28 270 top
C726  820uF  [CAP_E_6M3X9M0_P2M5]  154.97 67.5 270 top
C727  15nF  [CAP1005]  149.63 69.81 270 top
C728  390pF  [CAP1608]  149.63 71.71 90 top
C729  820uF  [CAP_E_6M3X9M0_P2M5]  162.21 67.5 270 top
C730  100uF  [CAP254X635_8_26H]  141.05 91.2 270 top
C800  1uF  [CAP1005_0_55H]  85.93 68.73 270 bottom
C801  1uF  [CAP1005_0_55H]  87.45 73.1 180 top
C841  1uF  [CAP1005_0_55H]  144.75 105.97 0 top
C843  0.1uF  [CAP1005]  19.05 45.6 0 top
C846  0.1uF  [CAP1005_0_55H]  19.09 82.86 0 bottom
C851  10uF  [CAP1608_2012_1_53H]  49.55 49 90 bottom
C852  10uF  [CAP1608_2012_1_53H]  54.05 46.7 270 bottom
C854  0.1uF  [CAP1005]  49.55 50.5 90 bottom
C855  33pF  [CAP1005]  53.35 44.2 180 bottom
C856  10uF  [CAP1608_2012_1_53H]  38.45 46.3 90 bottom
C858  1uF  [CAP1005_0_55H]  45.85 49 270 bottom
C861  10uF  [CAP1608_2012_1_53H]  49.45 36.1 90 bottom
C862  10uF  [CAP1608_2012_1_53H]  49.45 38 90 bottom
C864  0.1uF  [CAP1005]  49.45 34.6 90 bottom
C865  33pF  [CAP1005]  54.35 34.7 270 bottom
C866  10uF  [CAP1608_2012_1_53H]  67.93 19.57 180 bottom
C868  1uF  [CAP1005_0_55H]  48.55 27.2 0 bottom
C1001  8pF  [CAP1005]  21.47 16.49 180 top
C1002  8pF  [CAP1005]  21.45 20 180 top
C1003  8pF  [CAP1005]  21.47 23.49 180 top
C1004  12pF  [CAP1005]  14.75 14.7 0 top
C1005  12pF  [CAP1005]  14.75 17.1 0 top
C1006  12pF  [CAP1005]  14.75 19.5 0 top
C1007  12pF  [CAP1005]  25.35 30.3 180 bottom
C1008  12pF  [CAP1005]  25.35 27.9 0 bottom
C1010  68pF  [CAP1608]  6.1 94.11 180 top
C1011  1uF  [CAP1608_0_89H]  8.38 94.11 180 top
C1050  10nF  [CAP1005]  75.65 53 90 bottom
C1051  0.1uF  [CAP1005_0_55H]  81.09 53.84 0 bottom
C1052  1uF  [CAP1005_0_55H]  80.22 53.91 0 bottom
C1054  0.1uF  [CAP1005_0_55H]  79.94 52.05 45 bottom
C1055  1uF  [CAP1005_0_55H]  79.29 51.37 45 bottom
C1500  4.7uF  [CAP1608]  77.02 58.05 180 bottom
C1501  1uF  [CAP1005_0_55H]  78.21 59.35 180 bottom
C1502  0.1uF  [CAP1005_0_55H]  79.21 59.35 180 bottom
C1503  4.7uF  [CAP1608]  80.41 59.41 0 bottom
C1504  1uF  [CAP1005_0_55H]  81.81 59.69 225 bottom
C1505  0.1uF  [CAP1005_0_55H]  81.5 57.8 0 bottom
C1506  4.7uF  [CAP1608]  79.44 56.62 0 bottom
C1507  1uF  [CAP1005_0_55H]  80.56 56.26 180 bottom
C1508  0.1uF  [CAP1005_0_55H]  82.96 55.42 180 bottom
C1601  0.1uF  [CAP1005_0_55H]  19.25 33.3 270 top
C1602  0.1uF  [CAP1005_0_55H]  19.25 34.6 270 top
C1603  0.1uF  [CAP1005_0_55H]  19.25 35.6 270 top
C1604  0.1uF  [CAP1005_0_55H]  19.25 36.8 270 top
C1605  0.1uF  [CAP1005_0_55H]  19.25 38.7 270 top
C1606  0.1uF  [CAP1005_0_55H]  19.25 39.9 270 top
C1607  0.1uF  [CAP1005_0_55H]  19.25 40.9 270 top
C1608  0.1uF  [CAP1005_0_55H]  19.25 42.1 270 top
C1609  0.1uF  [CAP1005_0_55H]  19.25 25.3 270 top
C1610  0.1uF  [CAP1005_0_55H]  19.25 26.5 270 top
C1611  0.1uF  [CAP1005_0_55H]  19.25 27.5 270 top
C1612  0.1uF  [CAP1005_0_55H]  19.25 28.7 270 top
C1613  0.1uF  [CAP1005_0_55H]  19.25 31.1 270 top
C1614  0.1uF  [CAP1005_0_55H]  19.25 32.3 270 top
C1624  1uF  [CAP1608]  21.95 33.3 0 bottom
C1999  0.1uF  [CAP1005_0_55H]  26.16 33.04 180 bottom
C2001  8pF  [CAP1005]  6.75 67.8 270 top
C2002  8pF  [CAP1005]  9.15 66.9 270 top
C2003  8pF  [CAP1005]  11.65 67.7 270 top
C2004  12pF  [CAP1005]  6.75 72.5 270 top
C2005  12pF  [CAP1005]  9.15 72.5 270 top
C2006  12pF  [CAP1005]  11.65 72.5 270 top
C2509  4.7uF  [CAP1608]  73.49 65.08 90 bottom
C2510  1uF  [CAP1005_0_55H]  79.58 65.23 180 bottom
C2511  0.1uF  [CAP1005_0_55H]  80.58 65.21 180 bottom
C2512  4.7uF  [CAP1608]  76.06 66.14 45 bottom
C2513  1uF  [CAP1005_0_55H]  81.81 63.84 270 bottom
C2514  0.1uF  [CAP1005_0_55H]  72.92 64.16 270 bottom
C2515  4.7uF  [CAP1608]  77.2 67.25 45 bottom
C2516  1uF  [CAP1005_0_55H]  80.59 67.38 180 bottom
C2517  0.1uF  [CAP1005_0_55H]  82.25 66.95 180 bottom
C2530  0.1uF  [CAP1005_0_55H]  21.55 50.1 270 top
C2531  0.1uF  [CAP1005_0_55H]  21.55 51.1 270 top
C2532  0.1uF  [CAP1005_0_55H]  21.55 52.3 270 top
C2533  0.1uF  [CAP1005_0_55H]  21.55 53.3 270 top
C2534  0.1uF  [CAP1005_0_55H]  21.55 54.5 270 top
C2535  0.1uF  [CAP1005_0_55H]  33.05 85.1 270 top
C2536  0.1uF  [CAP1005_0_55H]  21.55 55.5 270 top
C2537  0.1uF  [CAP1005_0_55H]  21.55 56.7 270 top
C2538  0.1uF  [CAP1005_0_55H]  21.55 57.7 270 top
C2540  10uF  [CAP1608_2012_1_53H]  15.35 92.2 90 top
C2541  0.1uF  [CAP1005_0_55H]  33.05 86.1 270 top
C2722  1uF  [CAP1005_0_55H]  17.45 59.8 90 top
C3600  68pF  [CAP1005]  103.25 83 0 bottom
C3608  68pF  [CAP1005]  105.25 83 0 bottom
C4001  10uF  [CAP1608_2012_1_53H]  80.23 76.11 0 bottom
C4002  1uF  [CAP1005_0_55H]  81.67 74.94 180 bottom
C4003  100pF  [CAP1005]  91.85 92 90 top
C4004  2.2nF  [CAP1005]  75.95 89.2 90 top
C4008  1uF  [CAP1608_2012_1_53H]  164.21 28.29 180 top
C4013  1uF  [CAP1005_0_55H]  119.07 103.3 180 top
C4014  1uF  [CAP1005_0_55H]  117.92 103.3 180 top
C4015  1uF  [CAP1005_0_55H]  106.11 96.06 0 top
C4020  1uF  [CAP1005_0_55H]  85.27 58.44 270 bottom
C4070  4.7uF  [CAP1608]  62.54 91.3 180 top
C4071  0.1uF  [CAP1005_0_55H]  62.77 88.32 270 top
C4100  0.1uF  [CAP1005]  153.15 30.9 90 top
C4102  1uF  [CAP1608_2012POL]  153.95 25.3 90 top
C4103  1uF  [CAP1608_0_89H]  159.64 22.1 0 top
C4400  10nF  [CAP1005]  94.45 106.3 0 top
C4401  0.1uF  [CAP1005]  72.15 107.4 180 top
C4402  0.1uF  [CAP1005]  144.55 23.7 0 top
C4403  0.1uF  [CAP1005_0_55H]  22.85 74.6 270 top
C4404  0.1uF  [CAP1005_0_55H]  22.85 75.6 270 top
C4405  0.1uF  [CAP1005_0_55H]  22.85 76.6 270 top
C4406  0.1uF  [CAP1005_0_55H]  22.85 77.6 270 top
C4407  0.1uF  [CAP1005_0_55H]  22.85 78.6 270 top
C4408  0.1uF  [CAP1005_0_55H]  22.85 79.6 270 top
C4409  0.1uF  [CAP1005_0_55H]  22.85 80.6 270 top
C4410  0.1uF  [CAP1005_0_55H]  22.85 81.6 270 top
D601  BAT54KFILM  [DIOSOD_523]  60.75 106.1 270 top
D701  BAT54KFILM  [DIOSOD_523]  150.45 96.9 0 top
D1000  ESD5V3U1U-02LRH  [SMIND_TSSLP-2-1_0_40H]  12.25 15.2 0 top
D1001  ESD5V3U1U-02LRH  [SMIND_TSSLP-2-1_0_40H]  12.25 16.69 0 top
D1002  ESD5V3U1U-02LRH  [SMIND_TSSLP-2-1_0_40H]  12.25 18.7 0 top
D1003  ESD8V0R1B-02LRH  [SMIND_TSSLP-2-1_0_40H]  13.65 22.5 270 top
D1004  ESD8V0R1B-02LRH  [SMIND_TSSLP-2-1_0_40H]  13.65 23.8 270 top
D1005  ESD8V0R1B-02LRH  [SMIND_TSSLP-2-1_0_40H]  18.65 15.7 0 bottom
D1006  ESD8V0R1B-02LRH  [SMIND_TSSLP-2-1_0_40H]  18.65 17.4 0 bottom
D1600  RCLAMP0524P  [DIO_CLAMP_SLP2510P8]  13.72 35.05 270 top
D1601  RCLAMP0524P  [DIO_CLAMP_SLP2510P8]  13.72 26.33 270 top
D1602  RCLAMP0524P  [DIO_CLAMP_SLP2510P8]  13.72 40.39 270 top
D1603  RCLAMP0524P  [DIO_CLAMP_SLP2510P8]  13.72 31.24 90 top
D2500  ESD5V3U1U-02LRH  [SMIND_TSSLP-2-1_0_40H]  19.55 88.4 90 top
D2501  ESD5V3U1U-02LRH  [SMIND_TSSLP-2-1_0_40H]  19.55 87.1 90 top
D2502  ESD5V3U1U-02LRH  [SMIND_TSSLP-2-1_0_40H]  19.05 82.7 180 top
D2503  RCLAMP0524P  [DIO_CLAMP_SLP2510P8]  15.25 56.1 270 top
D2504  RCLAMP0524P  [DIO_CLAMP_SLP2510P8]  15.25 51.7 270 top
D4000  SML-010-L  [DIO_SML-010LTT87]  92.4 104.83 180 top
D4100  BAT54KFILM  [DIOSOD_523]  153.75 33 270 top
D4400  DIODE_SERIES  [SOT23_3PIN]  106.11 105.21 0 top
D4401  RCLAMP0524P  [DIO_CLAMP_SLP2510P8]  19.35 76.1 270 top
D4402  RCLAMP0524P  [DIO_CLAMP_SLP2510P8]  19.35 80.1 270 top
D4403  ESD5V3U1U-02LRH  [SMIND_TSSLP-2-1_0_40H]  15.05 59.8 90 top
D4404  ESD5V3U1U-02LRH  [SMIND_TSSLP-2-1_0_40H]  15.05 58.4 90 top
D4405  ESD5V3U1U-02LRH  [SMIND_TSSLP-2-1_0_40H]  16.05 86.4 180 top
D4406  ESD5V3U1U-02LRH  [SMIND_TSSLP-2-1_0_40H]  15.05 61.4 90 top
F400  nanoSMDC020F  [RES3216_1_3H]  51.05 22.9 180 top
F2501  NANOSMDC150F-2  [RES3216_1_3H]  12.95 94.3 90 top
HS2  HEATSINK_WVIA  [HS_7120181000G]  90.15 59 0 top
J1601  DVI_6SH  [CON_FOXCONN_PLASTRON_DI0B1-G-H0-LF-HF]  -0.91 23.89 270 top
J2501  DISPLAYPORT  [CON_DISPLAYPORT_ASTRON_R6890020]  0.18 82.88 270 top
J4004  CON08  [CON_2X4_SAMTEC_CLP_NOALIGN]  103.65 92.7 180 bottom
JU4001  HDR_1X2  [HD2MM1X2_KEY]  164.31 21.58 270 top
L601  0.6uH  [IND_TRIO_LD-10AM10003]  50.29 94.11 270 top
L611  0.47uH_7A  [IND_GUORUI_SCD0504T]  28.86 102.69 0 top
L701  0.6uH  [IND_TRIO_LD-10AM10003]  158.55 78.8 270 top
L1001  47nH  [RES1608_2012_1_1H]  17.15 14.7 270 top
L1002  47nH  [RES1608_2012_1_1H]  17.15 17.1 270 top
L1003  47nH  [RES1608_2012_1_1H]  17.15 19.5 270 top
L2001  47nH  [RES1608_2012_1_1H]  6.75 70.1 180 top
L2002  47nH  [RES1608_2012_1_1H]  9.15 70.1 180 top
L2003  47nH  [RES1608_2012_1_1H]  11.65 70.1 180 top
MB9  BLM15BD121SN1  [SMIND1005_0_5H]  95.26 69.22 180 bottom
MC130  4.7uF  [CAP1608]  143.97 54.32 0 bottom
MC131  4.7uF  [CAP1608]  142.91 50.59 0 bottom
MC132  4.7uF  [CAP1608]  104.67 67.5 90 bottom
MC133  4.7uF  [CAP1608]  143.71 79.85 0 bottom
MC174  10uF  [CAP1608_2012_1_53H]  86.41 59.99 90 bottom
MC175  10uF  [CAP1608_2012_1_53H]  74.33 81.2 0 bottom
MC176  10uF  [CAP1608_2012_1_53H]  91.1 56.08 270 bottom
MC177  10uF  [CAP1608_2012_1_53H]  58.43 88.32 90 top
MC196  4.7uF  [CAP1608]  82.13 79.25 90 bottom
MC364  4.7uF  [CAP1608]  128.41 36.74 270 top
MC365  4.7uF  [CAP1608]  143.4 63.31 0 top
MC366  4.7uF  [CAP1608]  142.9 50.59 180 top
MC367  4.7uF  [CAP1608]  143.38 63.31 180 bottom
MC368  4.7uF  [CAP1608]  143.72 79.85 180 top
MC369  4.7uF  [CAP1608]  142.4 59.34 0 top
MC378  4.7uF  [CAP1608]  143.29 36.18 180 bottom
MC379  4.7uF  [CAP1608]  143.29 36.28 0 top
MC380  4.7uF  [CAP1608]  126.6 48.98 90 bottom
MC381  4.7uF  [CAP1608]  142.47 59.4 180 bottom
MC382  4.7uF  [CAP1608]  114.47 88.92 90 bottom
MC383  4.7uF  [CAP1608]  128.69 78.85 270 top
MJ1001  G3179C219-005  [CON_WIESON_31796219]  -0.91 83.64 270 top
MJ2501  HDMI_TYPE  [CON_HDMI_RT_MOLEX500254]  -0.15 55.41 270 top
MPCIE1  x16 PCIe  [EDGECON_PCI_EXPRESS_16]  57.15 0 0 top
MR43  10K  [RES1005]  66.85 59.48 90 top
MR44  10K  [RES1005]  88.25 87.2 90 top
MR45  10K  [RES1005]  88.35 79.8 180 top
MR46  10K  [RES1005]  95.45 86.71 0 bottom
MR47  10K  [RES1005]  92.59 86.69 0 bottom
MR48  1K  [RES1005]  97.05 89.3 180 top
MR49  1K  [RES1005]  95.05 89.3 180 top
MR50  10K  [RES1005]  93.85 89.3 180 top
MR51  10K  [RES1005]  29.99 24.86 270 bottom
MR52  10K  [RES1005]  29.99 23.84 270 bottom
MR53  10K  [RES1005]  80.05 88.8 90 top
MR54  10K  [RES1005]  89.2 71.48 0 bottom
MR55  10K  [RES1005]  98.25 89.3 180 top
MR56  10K  [RES1005]  66.86 60.35 90 top
MR57  10K  [RES1005]  75.63 83.53 90 top
MR58  10K  [RES1005]  86.85 79.8 180 top
MR70  5.1K  [RES1005]  72.25 69.44 90 bottom
MR71  5.1K  [RES1005]  65.82 65.16 270 bottom
MR75  182R  [RES1005]  65.83 69 90 bottom
MR850  0R  [RES1608_2012]  54.05 51.4 90 bottom
MR858  0.1R  [RES3225_0_7H]  40.37 49.98 180 bottom
MR870  3.3R  [RES3216]  61.25 18.34 0 bottom
MR871  3.3R  [RES3216]  65.05 18.34 0 bottom
MR872  3.3R  [RES3216]  54.09 18.44 0 bottom
MR873  3.3R  [RES3216]  57.85 18.34 0 bottom
MR1015  0R  [RES1005]  22.47 17.49 180 top
MR1016  0R  [RES1005]  22.47 20.99 180 top
MR1017  0R  [RES1005]  22.47 24.49 180 top
MR1018  0R  [RES1005]  23.75 30.8 90 bottom
MR1019  0R  [RES1005]  23.75 28.4 90 bottom
MR1027  0R  [RES1005]  24.47 17.49 180 top
MR1028  0R  [RES1005]  24.47 20.99 180 top
MR1029  0R  [RES1005]  24.47 24.49 180 top
MR1240  10K  [RES1005]  96.05 89.3 180 top
MR1241  10K  [RES1005]  81.41 84.46 90 top
MR2014  0R  [RES1005]  33.45 34.64 180 bottom
MR2721  0R  [RES1005]  34.58 34.66 180 bottom
MR4076  0R  [RES1005]  64.29 93.06 0 top
MT200  MOUNTING_8PINS  [MTG3_4_8VIAS]  5.84 105.33 0 top
MU861  UP7706ADC8  [VDFN8_THERMAL_1_00H]  52.44 29.69 180 bottom
NOREF  -  []  9.02 205.6 0 top
NOREF#2  -  []  9.02 183.6 0 top
NOREF#3  -  []  171.45 0 0 top
NOREF#4  -  [unnamed#2]  24.13 12.75 0 top
NOREF#5  -  [unnamed#3]  162.56 5.08 0 top
NOREF#6  -  []  80.92 161.54 0 top
NOREF#7  -  []  44.26 205.69 0 top
NOREF#8  -  []  0 4.5 0 top
NOREF#9  -  []  80.92 205.54 0 top
NOREF#10  -  []  -10.98 -19.07 0 top
NOREF#11  -  []  229.69 182.13 0 top
NOREF#12  -  []  231.52 46.1 0 top
NOREF#13  -  [unnamed#4]  90.15 59 0 top
NOREF#14  -  []  80.92 183.54 0 top
NOREF#15  -  []  173.93 110.44 0 top
NOREF#16  -  []  140.41 -51.59 0 top
NOREF#17  -  []  0 0 0 top
NOREF#18  -  []  169.15 11.66 0 top
NOREF#19  -  []  79.91 31.94 0 top
NOREF#20  -  [unnamed#5]  152.4 12.75 0 top
NOREF#21  -  []  306.65 216.5 0 top
NOREF#22  -  [unnamed#3]  24.13 5.08 0 top
NOREF#23  -  [unnamed#3]  165.11 15.84 0 top
NOREF#24  -  []  86.67 41.09 0 top
NOREF#25  -  []  235.87 201.66 0 top
NOREF#26  -  [unnamed#2]  162.56 12.75 0 top
NOREF#27  -  []  78.35 0 0 top
NOREF#28  -  [unnamed#3]  166.29 109.8 0 top
NOREF#29  -  [unnamed#3]  12.84 12.14 0 top
NOREF#30  -  []  9.02 161.6 0 top
NOREF#31  -  [unnamed#6]  90.15 59 0 top
NOREF#32  -  []  139.45 1.6 0 top
NOREF#33  -  []  151.55 49.9 0 top
NOREF#34  -  []  272.65 225 0 top
NOREF#35  -  []  171.45 0 90 top
NOREF#36  -  [unnamed#3]  166.29 109.8 180 bottom
NOREF#37  -  []  60.19 66.7 180 bottom
NOREF#38  -  [unnamed#3]  165.11 15.84 180 bottom
NOREF#39  -  []  271.52 46.1 180 bottom
NOREF#40  -  [unnamed#3]  12.81 12.12 180 bottom
NOREF#41  -  []  67.22 52.76 180 bottom
NR75  0R  [RES1005]  65.33 70.67 90 bottom
NR4000  2.2K  [RES1005]  92.13 99.16 90 bottom
NS600  NS_VIA  [NET_SHORT]  88.21 56.11 180 bottom
NS700  NS_VIA  [NET_SHORT]  139.25 100.4 90 top
Q1  BSH111  [SOT23_3PIN]  57.95 19.5 180 top
Q2  BSH111  [SOT23_3PIN]  54.15 19.5 180 top
Q601  MOS_N_4D_3S_TH  [SO8_POWERPAK_1_1H]  43.43 102.87 90 top
Q603  MOS_N_4D_3S_TH  [SO8_POWERPAK_1_1H]  51.82 102.87 90 top
Q701  MOS_N_4D_3S_TH  [SO8_POWERPAK_1_1H]  148.97 91.06 90 top
Q703  MOS_N_4D_3S_TH  [SO8_POWERPAK_1_1H]  158.5 91.06 90 top
Q840  MMBT3904  [SOT23_3PIN]  141.05 105.8 0 top
Q841  MMBT3904  [SOT23_3PIN]  130.95 106 90 top
Q842  MMBT3904  [SOT23_3PIN]  135.05 105.8 180 top
Q850  MMBT3904  [SOT23_3PIN]  20.84 79.47 270 bottom
Q851  MMBT3904  [SOT23_3PIN]  20.89 74.51 270 bottom
Q852  MMBT3904  [SOT23_3PIN]  74.55 106.5 180 top
Q1200  MOS_N  [SOT23_3PIN]  70.49 106.31 180 bottom
Q1201  MOS_N  [SOT23_3PIN]  74.49 106.31 180 bottom
Q1601  MOS_N  [SOT23_3PIN]  16.55 46.7 180 top
Q1602  MMBT3904  [SOT23_3PIN]  32.15 19.9 180 bottom
Q1801  MOS_N  [SOT23_3PIN]  22.95 86.3 90 top
Q1802  MOS_N  [SOT23_3PIN]  22.95 90.15 90 top
Q1803  NPN  [SOT23_3PIN]  30.35 81.4 180 top
Q1804  MOS_N  [SOT23_3PIN]  26.35 81.4 180 top
Q2513  MMBT3904  [SOT23_3PIN]  19 71.29 180 top
Q2701  MOS_N  [SOT23_3PIN]  21.55 46.7 0 top
Q4006  MMBT3904  [SOT23_3PIN]  110.69 99.49 0 top
Q4007  MMBT3904  [SOT23_3PIN]  115.26 99.49 0 top
Q4008  MMBT3906  [SOT23_3PIN_1_1H]  115.26 105.21 0 top
Q4009  MMBT3904  [SOT23_3PIN]  106.11 99.49 0 top
Q4010  MMBT3904  [SOT23_3PIN]  69.96 106.4 180 top
Q4011  MMBT3904  [SOT23_3PIN]  147.25 24.5 270 top
Q4013  MMBT3904  [SOT23_3PIN]  96.97 99.49 0 top
Q4014  2N7002E  [SOT23_3PIN]  110.69 105.21 0 top
Q4016  MMBT3904  [SOT23_3PIN]  101.54 99.49 0 top
Q4050  MMBT3904  [SOT23_3PIN]  92.4 99.49 0 top
Q4100  MMBT3904  [SOT23_3PIN]  158.5 28.29 270 top
Q4101  MMBT3906  [SOT23_3PIN_1_1H]  153.92 28.29 270 top
Q4102  MMBT3906  [SOT23_3PIN_1_1H]  147.25 28.3 270 top
Q4103  NPN_2C  [SOT223]  153.92 20.67 90 top
Q4400  MMBT3906  [SOT23_3PIN_1_1H]  101.54 105.21 0 top
Q4401  MMBT3904  [SOT23_3PIN]  96.97 105.21 0 top
Q4402  MMBT3904  [SOT23_3PIN]  23.05 71.2 0 top
R1  45.3K  [RES1005]  55.15 16.8 270 top
R2  45.3K  [RES1005]  51.35 18.6 0 top
R3  0R  [RES1005]  53.45 16.1 0 top
R4  0R  [RES1005]  52.35 16.1 0 top
R7  1K  [RES1005]  84.01 60.24 180 bottom
R8  2.0K  [RES1005]  87.13 53.88 180 bottom
R9  1.27K  [RES1005]  86.85 56.1 0 bottom
R12  499R  [RES1005]  84.02 55.43 180 bottom
R13  33R  [RES1005]  80.05 89.7 90 top
R14  33R  [RES1005]  89.95 86.5 180 top
R15  33R  [RES1005]  90.45 89.2 180 top
R16  33R  [RES1005]  80.05 92.4 90 top
R21  221R  [RES1005]  74.15 60.7 270 bottom
R22  110R  [RES1005]  75.9 61.55 0 bottom
R23  715R  [RES1005]  79.92 63.53 90.1 bottom
R24  10K  [RES1005]  80.05 91.5 270 top
R30  0R  [RES1005]  69.05 32.1 0 top
R31  1M  [RES1005]  68.05 32.1 180 top
R32  10K  [RES1005]  88.05 71.5 180 bottom
R33  4.7K  [RES1005]  88.35 85.3 90 top
R34  4.7K  [RES1005]  88.35 84.4 90 top
R35  1K  [RES1005]  83.32 53.48 270 bottom
R36  0R  [RES1005]  70.15 32.1 180 top
R37  1K  [RES1005]  101.45 86.1 180 bottom
R38  1K  [RES1005]  104.95 92.7 0 top
R39  1K  [RES1005]  104.95 90.3 0 top
R43  10K  [RES1005]  67.85 59.48 270 top
R44  10K  [RES1005]  88.25 86.3 90 top
R45  10K  [RES1005]  88.35 80.8 0 top
R46  10K  [RES1005]  95.43 87.69 180 bottom
R47  10K  [RES1005]  92.59 87.69 180 bottom
R48  1K  [RES1005]  97.05 90.3 0 top
R49  1K  [RES1005]  95.05 90.3 0 top
R50  10K  [RES1005]  93.85 90.3 0 top
R51  10K  [RES1005]  30.97 24.86 90 bottom
R52  10K  [RES1005]  30.99 23.84 90 bottom
R53  10K  [RES1005]  80.05 90.6 90 top
R54  10K  [RES1005]  89.2 72.48 180 bottom
R55  10K  [RES1005]  98.25 90.3 0 top
R56  10K  [RES1005]  67.86 60.35 270 top
R57  10K  [RES1005]  74.64 83.53 90 top
R58  10K  [RES1005]  86.85 80.8 0 top
R59  1K  [RES1005]  88.3 63.6 270 bottom
R60  1K  [RES1005]  91.55 64.3 0 bottom
R61  0R  [RES1005]  57.25 11.7 270 top
R63  10K  [RES1005]  59.65 11.7 270 top
R65  0R  [RES1005]  60.25 13.4 0 top
R70  5.1K  [RES1005]  72.25 70.44 270 bottom
R71  5.1K  [RES1005]  65.83 66.38 90 bottom
R72  0R  [RES1005]  86.21 61.47 270 bottom
R73  0R  [RES1005]  74.01 68.46 270 bottom
R74  0R  [RES1005]  72.55 67.89 180 bottom
R75  182R  [RES1005]  71.63 67.89 180 bottom
R76  221R  [RES1005]  70.24 66.27 90 bottom
R201  4.99K  [RES1005]  142.95 47.6 270 top
R202  4.99K  [RES1005]  142.95 46.7 90 top
R203  4.99K  [RES1005]  128.55 47.4 90 top
R204  4.99K  [RES1005]  128.55 46.5 270 top
R205  4.99K  [RES1005]  142.95 67.9 270 top
R206  4.99K  [RES1005]  142.95 68.9 90 top
R207  4.99K  [RES1005]  127.43 70.2 0 bottom
R208  4.99K  [RES1005]  128.43 70.19 180 bottom
R209  4.99K  [RES1005]  127.25 43.7 180 bottom
R210  4.99K  [RES1005]  128.15 43.7 0 bottom
R211  4.99K  [RES1005]  142.95 42.1 270 top
R212  4.99K  [RES1005]  142.95 43.1 90 top
R213  4.99K  [RES1005]  128.45 73.8 90 top
R214  4.99K  [RES1005]  128.45 72.9 270 top
R215  4.99K  [RES1005]  142.94 72.94 90 bottom
R216  4.99K  [RES1005]  142.94 71.94 270 bottom
R217  243R  [RES1005]  142.95 44.9 90 top
R218  243R  [RES1005]  128.55 44.7 270 top
R219  243R  [RES1005]  142.94 70.97 90 top
R220  243R  [RES1005]  128.65 71.8 90 bottom
R221  56R  [RES1005]  127.13 51.53 270 top
R222  56R  [RES1005]  127.16 50.23 90 top
R223  56R  [RES1005]  127.05 64.38 270 top
R224  56R  [RES1005]  127.05 63.08 90 top
R225  10K  [RES1005]  139.07 57.03 180 bottom
R226  0R  [RES1005]  105.35 55.76 225 bottom
R227  10K  [RES1005]  140.09 59.74 225 bottom
R228  0R  [RES1005]  132.97 60.58 45 bottom
R229  10K  [RES1005]  140.1 56.99 0 bottom
R230  10K  [RES1005]  140.86 60.47 45 bottom
R291  100R  [RES1005]  99.45 45.85 90 bottom
R292  100R  [RES1005]  96.85 46.95 180 bottom
R293  100R  [RES1005]  99.45 46.85 90 bottom
R294  100R  [RES1005]  97.9 48.52 270 bottom
R296  51.1R  [RES1005]  92.63 74.69 0 bottom
R297  51.1R  [RES1005]  93.53 74.69 0 bottom
R298  150R  [RES1005]  101.25 83 0 bottom
R301  243R  [RES1005]  96.97 50.2 270 bottom
R302  243R  [RES1005]  95.94 53.81 0 bottom
R303  243R  [RES1005]  96.03 51.81 270 bottom
R436  1K  [RES1005]  101.45 88.5 180 bottom
R595  0R  [RES1608_2012]  85.59 76.37 0 bottom
R596  0R  [RES1005]  85.95 84.4 270 top
R597  0R  [RES1005]  85.95 85.3 270 top
R600  0R  [RES1608]  71.55 96.3 180 top
R607  2.2R  [RES1608_2012]  66.73 97.36 180 top
R608  0R  [RES3216]  28.86 101.29 270 top
R609  0R  [RES1005]  71.25 101.8 180 top
R610  154K  [RES1005]  69.45 101.8 270 top
R611  4.99K  [RES1005]  69.45 99.8 90 top
R612  2.94K  [RES1005]  73.05 102.3 90 top
R613  3.65K  [RES1005]  69.45 100.8 90 top
R614  0R  [RES1005]  69.45 102.8 90 top
R615  42.2K  [RES1005]  61.02 98.12 0 top
R616  0R  [RES3216]  28.86 104.09 270 top
R619  300R  [RES1608_2012]  50.67 107.06 270 top
R621  0R  [RES1005]  45.95 106.4 90 top
R622  0R  [RES1608]  58.75 98.6 270 top
R700  0R  [RES1608]  139.05 101.9 90 top
R702  0R  [RES3216]  137.25 96.5 180 top
R707  2.2R  [RES1608_2012]  148.45 105.9 0 top
R709  0R  [RES1005]  141.95 101 90 top
R710  10.5K  [RES1005]  144.32 101.98 270 top
R711  4.99K  [RES1005]  144.32 103.98 270 top
R712  2.94K  [RES1005]  142.85 100 270 top
R713  3.65K  [RES1005]  144.32 102.98 270 top
R714  0R  [RES1005]  144.32 100.98 270 top
R715  42.2K  [RES1005]  154.95 103.6 180 top
R719  1R  [RES1608_2012]  158.75 86 90 top
R721  0R  [RES1005]  154.55 99.7 0 top
R722  0R  [RES1608]  156.95 102.5 0 top
R839  0R  [RES1005]  55.65 24.1 180 bottom
R841  4.75K  [RES1005]  143.6 105.97 180 top
R843  5.1K  [RES1005]  150.95 106.5 0 top
R844  10K  [RES1005]  19.05 48 0 top
R845  5.1K  [RES1005]  138.65 106.7 180 top
R846  5.1K  [RES1005]  137.55 106.7 180 top
R849  10K  [RES1005]  56.95 24.1 180 bottom
R850  2.32K  [RES1005]  21.74 71.97 270 bottom
R851  1K  [RES1005]  21.74 76.97 270 bottom
R852  11.3K  [RES1005]  21.38 82.86 0 bottom
R853  1K  [RES1005]  22.52 82.86 0 bottom
R854  10K  [RES1005]  51.15 43.2 180 bottom
R855  2.67K  [RES1005]  52.35 44.2 180 bottom
R856  0R  [RES1005]  45.85 47.9 90 bottom
R857  10K  [RES1005]  20.23 82.86 180 bottom
R858  0.05R_0.5W  [RES3216]  40.34 49.99 180 bottom
R859  10K  [RES1005]  43.75 41.2 90 bottom
R860  0R  [RES3216]  55.05 37.4 270 bottom
R862  10K  [RES1005]  53.05 24.1 0 bottom
R863  10K  [RES1005]  54.35 24.1 0 bottom
R864  10K  [RES1005]  56.95 35.7 270 bottom
R865  13.0K  [RES1005]  54.35 35.7 270 bottom
R866  0R  [RES1005]  48.55 32.1 0 bottom
R870  3.6R  [RES3225_0_7H]  61.35 18.36 0 bottom
R871  3.6R  [RES3225_0_7H]  65 18.35 0 bottom
R872  3.6R  [RES3225_0_7H]  53.99 18.44 0 bottom
R873  3.6R  [RES3225_0_7H]  57.82 18.41 0 bottom
R880  0R  [RES3216]  53.95 49 270 bottom
R1001  75R  [RES1005]  23.47 23.49 0 top
R1002  75R  [RES1005]  23.47 19.99 0 top
R1003  75R  [RES1005]  23.47 16.49 0 top
R1005  2.2K  [RES1005]  16.85 22.5 270 top
R1006  33R  [RES1005]  15.85 22.5 270 top
R1008  2.2K  [RES1005]  16.85 23.8 270 top
R1009  33R  [RES1005]  15.85 23.8 270 top
R1010  10R  [RES1005]  26.45 30.3 0 bottom
R1011  10R  [RES1005]  26.45 27.9 180 bottom
R1015  0R  [RES1005]  22.47 16.49 0 top
R1016  0R  [RES1005]  22.47 19.99 0 top
R1017  0R  [RES1005]  22.47 23.49 0 top
R1018  0R  [RES1005]  24.25 30.3 180 bottom
R1019  0R  [RES1005]  24.25 27.9 180 bottom
R1027  37.4R  [RES1005]  24.47 16.49 0 top
R1028  37.4R  [RES1005]  24.47 19.99 0 top
R1029  37.4R  [RES1005]  24.47 23.49 0 top
R1225  78.7K  [RES1005]  68.35 97.8 0 top
R1226  158K  [RES1005_0_4H]  69.35 97.8 0 top
R1240  10K  [RES1005]  96.05 90.3 180 top
R1241  10K  [RES1005]  82.4 84.47 90 top
R1500  150R  [RES1005]  83.14 57.78 180 bottom
R1601  499R  [RES1005]  16.85 33.3 90 top
R1602  499R  [RES1005]  16.85 34.6 90 top
R1603  499R  [RES1005]  16.85 35.6 270 top
R1604  499R  [RES1005]  16.85 36.8 270 top
R1605  499R  [RES1005]  16.85 38.7 270 top
R1606  499R  [RES1005]  16.85 39.9 270 top
R1607  499R  [RES1005]  16.85 40.9 270 top
R1608  499R  [RES1005]  16.85 42.1 270 top
R1609  499R  [RES1005]  16.85 25.3 270 top
R1610  499R  [RES1005]  16.85 26.5 270 top
R1611  499R  [RES1005]  16.85 27.5 270 top
R1612  499R  [RES1005]  16.85 28.7 270 top
R1613  499R  [RES1005]  16.85 31.1 270 top
R1614  499R  [RES1005]  16.85 32.3 270 top
R1617  10K  [RES1005]  31.05 16.6 180 bottom
R1618  10K  [RES1005]  32.75 17.2 90 bottom
R1804  10K  [RES1005]  25.65 87 0 bottom
R1805  10K  [RES1005]  32.75 82.4 0 top
R2001  75R  [RES1005]  11.65 66.8 270 top
R2002  75R  [RES1005]  9.15 67.8 270 top
R2003  75R  [RES1005]  6.75 66.9 270 top
R2005  2.2K  [RES1005]  18.55 89.5 270 top
R2006  33R  [RES1005]  16.05 89.6 270 top
R2008  2.2K  [RES1005]  18.55 90.7 270 top
R2009  33R  [RES1005]  16.05 90.6 270 top
R2014  0R  [RES1005]  33.45 33.64 0 bottom
R2027  37.4R  [RES1005]  6.75 66 270 top
R2028  37.4R  [RES1005]  9.15 66 270 top
R2029  37.4R  [RES1005]  11.65 65.9 270 top
R2500  150R  [RES1005]  82.85 65.36 90 bottom
R2522  100K  [RES1005]  30.65 84.9 90 top
R2523  100K  [RES1005]  30.65 86.3 270 top
R2524  1M  [RES1005]  20.25 83.1 180 top
R2526  1M  [RES1005]  19.05 84.8 0 top
R2527  10K  [RES1005]  19.59 73.76 270 top
R2530  10K  [RES1005]  16.6 72.09 0 top
R2701  2.2K  [RES1005]  21.42 60.24 90 top
R2703  2.2K  [RES1005]  21.42 61.54 90 top
R2713  499R  [RES1005]  19.05 50 90 top
R2714  499R  [RES1005]  19.05 51.2 90 top
R2715  499R  [RES1005]  19.05 52.2 90 top
R2716  499R  [RES1005]  19.05 53.4 90 top
R2717  499R  [RES1005]  19.05 54.4 90 top
R2718  499R  [RES1005]  19.05 55.6 90 top
R2719  499R  [RES1005]  19.05 56.6 90 top
R2720  499R  [RES1005]  19.05 57.8 90 top
R2721  0R  [RES1005]  34.58 33.66 0 bottom
R3600  10K  [RES1005]  102.25 83 180 bottom
R3615  680R  [RES1005]  104.25 83 0 bottom
R3616  0R  [RES1005]  106.25 83 180 bottom
R4001  100R  [RES1005]  72.77 95.63 0 top
R4002  100R  [RES1005]  73.91 95.63 0 top
R4011  10K  [RES1005]  75.06 98.3 0 top
R4017  4.7K  [RES1005]  72.77 98.3 0 top
R4018  4.7K  [RES1005]  73.91 98.3 0 top
R4038  2.2K  [RES1005]  100.25 91.6 0 top
R4039  1K  [RES1005]  100.25 89.2 0 top
R4040  5.1K  [RES1005]  117.92 100.25 180 top
R4043  470K  [RES1005]  112.97 107.87 270 top
R4044  1K  [RES1005]  119.07 100.25 180 top
R4045  10K  [RES1005]  100.78 95.3 90 top
R4046  5.1K  [RES1005]  104.97 96.06 180 top
R4047  100K  [RES1005]  103.83 96.06 180 top
R4050  0R  [RES1005]  100.78 96.44 270 top
R4051  1K  [RES1005]  88.81 98.36 180 top
R4052  0R  [RES1005]  107.35 96.1 180 top
R4053  100K  [RES1005]  72.15 105.1 0 top
R4054  1K  [RES1005]  95.45 95.3 90 top
R4055  20K  [RES1005]  110.3 107.87 90 top
R4056  3.9R  [RES1005]  111.35 102.6 90 top
R4057  1K  [RES1005]  144.55 26.1 180 top
R4058  1K  [RES1005]  89.75 98.3 180 top
R4059  499R  [RES1005]  90.11 105.97 0 top
R4060  1K  [RES1005]  102.68 96.06 180 top
R4061  20K  [RES1005]  95.45 96.44 90 top
R4062  0R  [RES1005]  108.65 96.1 180 top
R4063  100K  [RES1005]  143.55 23.7 0 top
R4065  0R  [RES1005]  73.15 90 0 top
R4070  200R  [RES1005]  69.45 89 270 top
R4071  200R  [RES1005]  69.45 89.8 270 top
R4072  300K  [RES1005]  69.45 90.9 90 top
R4073  300K  [RES1005]  69.45 92 90 top
R4075  1.8R  [RES1005]  62.77 89.22 90 top
R4076  0R  [RES1005]  65.15 93.06 180 top
R4077  0R  [RES1005]  66.01 93.06 180 top
R4078  0R  [RES1005]  70.35 97.8 180 top
R4080  0R  [RES1005]  76.2 95.63 0 top
R4081  33R  [RES1005]  77.75 89 0 top
R4100  2.61K  [RES1005]  74.35 88.3 90 top
R4101  10K  [RES1005]  157.95 30.9 270 top
R4102  1K  [RES1005]  160.55 32.3 180 top
R4103  22K  [RES1005]  153.15 31.9 270 top
R4105  1K  [RES1005]  155.55 30.9 270 top
R4106  1K  [RES1005]  150.65 25.3 270 top
R4107  820R  [RES1005]  157.15 24.1 0 top
R4108  1M  [RES1005]  144.55 28.6 0 top
R4110  0R  [RES1608_2012]  159.64 18.29 0 top
R4111  1K  [RES1005]  155.55 31.9 90 top
R4112  5.1K  [RES1005]  161.55 32.3 180 top
R4113  6.8K  [RES1005]  162.55 32.3 0 top
R4400  47K  [RES1005]  104.97 107.87 90 top
R4401  47K  [RES1005]  76.2 98.3 0 top
R4402  47K  [RES1005]  102.55 107.9 90 top
R4403  100K  [RES1005]  92.95 107.9 270 top
R4404  20K  [RES1005]  100.15 107.9 90 top
R4405  20K  [RES1005]  95.35 107.9 270 top
R4406  0R  [RES1005]  89.75 100.7 0 top
R4407  20K  [RES1005]  97.75 107.9 270 top
R4408  1K  [RES1005]  88.81 100.46 0 top
R4409  10K  [RES1005]  25.4 69.7 0 top
R4410  10K  [RES1005]  17.15 61.4 270 top
R4411  1R  [RES1608_2012]  42.54 24.44 0 top
R4412  1R  [RES1608_2012]  37.94 24.44 0 top
R4413  1R  [RES1608_2012]  40.24 24.44 0 top
SW4001  DIP_SWX2  [SW_CK-2]  96.76 93.61 180 bottom
SW4002  DIP_SWX2  [SW_CK-2]  91.98 93.68 180 bottom
TP58  TP_22mil_SM_top  [TP089X043]  89.51 64.54 270 bottom
TP59  TP_22mil_SM_top  [TP089X043]  87.91 68.63 270 bottom
TP91  TP_22mil_SM_top  [TP089X043]  96.95 83.59 270 top
TP94  TP_22mil_SM_top  [TP089X043]  92.05 69.2 180 bottom
TP97  TP_22mil_SM_top  [TP089X043]  88.25 64.2 270 bottom
TP101  TP_22mil_SM_top  [TP089X043]  73.15 26 90 top
TP102  TP_22mil_SM_top  [TP089X043]  74.45 26 90 top
TP103  TP_22mil_SM_top  [TP089X043]  76.15 26 90 top
TP104  TP_22mil_SM_top  [TP089X043]  77.45 26 90 top
TP105  TP_22mil_SM_top  [TP089X043]  78.75 26 90 top
TP106  TP_22mil_SM_top  [TP089X043]  80.05 26 90 top
TP107  TP_22mil_SM_top  [TP089X043]  83.55 21.12 90 top
TP108  TP_22mil_SM_top  [TP089X043]  84.75 21.12 90 top
TP109  TP_22mil_SM_top  [TP089X043]  87.55 21.12 90 top
TP110  TP_22mil_SM_top  [TP089X043]  88.75 21.12 90 top
TP111  TP_22mil_SM_top  [TP089X043]  96.55 23.3 90 top
TP112  TP_22mil_SM_top  [TP089X043]  97.75 23.3 90 top
TP113  TP_22mil_SM_top  [TP089X043]  100.55 23.3 90 top
TP114  TP_22mil_SM_top  [TP089X043]  101.75 23.3 0 top
TP115  TP_22mil_SM_top  [TP089X043]  108.55 19.8 0 top
TP116  TP_22mil_SM_top  [TP089X043]  109.75 19.8 0 top
TP117  TP_22mil_SM_top  [TP089X043]  112.55 15.4 0 top
TP118  TP_22mil_SM_top  [TP089X043]  113.75 15.4 0 top
TP119  TP_22mil_SM_top  [TP089X043]  120.55 13.1 0 top
TP120  TP_22mil_SM_top  [TP089X043]  121.75 13.1 0 top
TP121  TP_22mil_SM_top  [TP089X043]  124.55 11.1 0 top
TP122  TP_22mil_SM_top  [TP089X043]  125.75 11.1 0 top
TP123  TP_22mil_SM_top  [TP089X043]  76.07 62.98 0 top
TP500  22mil  [TP089X043]  84.31 77.8 180 bottom
TP501  22mil  [TP089X043]  84.15 84.4 270 top
TP502  22mil  [TP089X043]  84.15 85.5 270 top
TP503  22mil  [TP089X043]  84.14 75.54 180 bottom
TP1700  TP_22mil_SM_top  [TP089X043]  12.85 57.2 0 top
TR75  0R  [RES1005]  65.83 69.83 90 bottom
U1  CAICOS_DDR3  [BGA0_8X1_0MM23X23-631]  90.15 59 270 top
U2  PM25LV010A-100SCE  [SO8_1_78H]  85.55 90.6 270 top
U4  NC7SZ08P5X_NL  [SOT353_1_1H]  57.65 13.4 90 top
U12  IDT6V40088NBGI8  [TDFN10_3M0X3M0X0M8_P0M50_TH]  69.05 68.59 180 bottom
U201  23E22387MNG8  [BGA0_8MM10X16-100]  135.76 42.81 0 bottom
